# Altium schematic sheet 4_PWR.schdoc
size 307 x 218 mm; Symbol: Drawing-Symbol_A4; Device: Drawing-Symbol_A4; @Project Name: Bed Temp Regulation; @Page Count: 4; @Update Date: 2026-02-17; @Create Date: 2026-02-16; @Schematic Name: Schematic Main; @Page No: 4; @Page Name: PWR; Company: EasyEDA.com; Version: V1.0; Page Size: A4; @Create Time: 11:43:01; @Update Time: 14:13:41; Width: 1170; Height: 825; Region Start: 1; X Region Count: 6; Y Region Count: 4; Blade Width: 10; Title Block Position: 3; @Board Name: Main Board
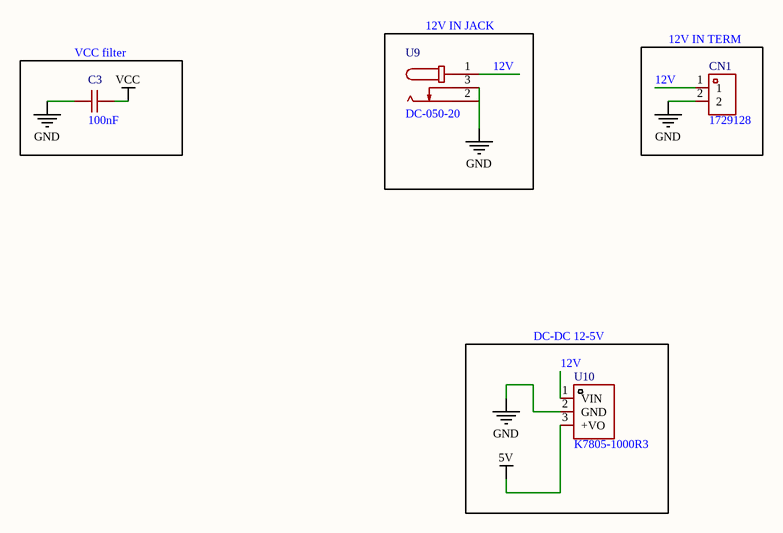
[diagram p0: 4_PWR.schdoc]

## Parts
C3  100nF  [C0805]
CN1  1729128  [CONN-TH_2P-P5.08_1729128]
U9  DC-050-20  [DC-IN-SMD_DC-050-20A]
U10  K7805-1000R3  [PWRM-TH_YLPTEC_K78XX-1000R3]

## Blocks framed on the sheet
12V IN JACK: U9
12V IN TERM: CN1
VCC filter: C3
DC-DC 12-5V: U10

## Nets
5V: U10.3(+VO)
GND: C3.1 CN1.2 U9.2 U9.3 U10.2(GND)
VCC: C3.2
12V: CN1.1 U9.1 U10.1(VIN)

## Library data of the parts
C3 = CL21B104KCFNNNE: Manufacturer: SAMSUNG(三星); Add into BOM: yes; Tolerance: ±10%; Voltage Rating: 100V; Temperature Coefficient: X7R
CN1 = 1729128_C7509570: Manufacturer: Phoenix Contact(菲尼克斯); Add into BOM: yes
U9 = DC-050-20: Manufacturer: HanElectricity(瀚源); Add into BOM: yes; Connector Type: DC Power Jack; Inside Contact Diameter: 2mm; Outside Contact Diameter: 6mm
U10 = K7805-1000R3: Manufacturer: YLPTEC(易川); Symbol: K7805-1000R3_C2992391; Add into BOM: yes; Function: Buck-Boost; Number of Outputs: 1; Voltage - Supply: 8V~36V; Output Voltage Accuracy: ±3%; Output Voltage: 5V; Output Current(Max): 1A; Conversion Efficiency: 93%; Capacitive Load(Max): 680uF; Supply Current (Iq): 1mA; Switching Frequency: 500kHz; Ripple Noise: 60mVp-p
